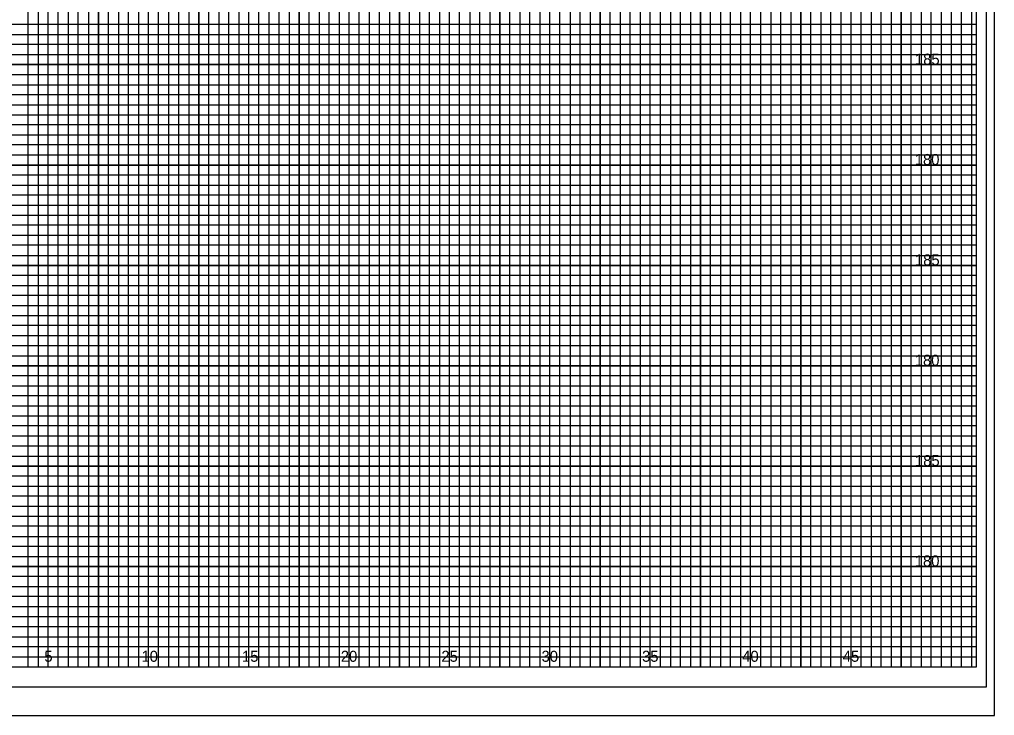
# Model space of a CAD drawing. Extents: x -4 to 103, y -2 to 209.
# Drawn here: x 54.82 to 103.4, y 68.4 to 103.08 of the extents above; entities that cross this region are included whole.
import ezdxf

# ---------------------------------------------------------------- set-up
doc = ezdxf.new("R2010")
doc.units = 0
for name, color, linetype in [('Old_Level_10', 7, 'Continuous'), ('Old_Level_16', 7, 'Continuous'), ('Old_Level_3', 7, 'Continuous'), ('Old_Level_4', 7, 'Continuous'), ('Old_Level_5', 7, 'Continuous'), ('Old_Level_6', 7, 'Continuous'), ('Old_Level_8', 7, 'Continuous'), ('Prop Dimension', 7, 'Continuous'), ('Prop XS Subgrade Earthwork', 7, 'Continuous')]:
    doc.layers.add(name, color=color, linetype=linetype)

msp = doc.modelspace()

# ---------------------------------------------------------------- linework, layer by layer
at = {"layer": 'Old_Level_10'}
for p, q in [((56.25, 70.825), (56.25, 135.825)), ((58.75, 70.825), (58.75, 135.825)), ((61.25, 70.825), (61.25, 135.825)), ((63.75, 70.825), (63.75, 135.825)), ((66.25, 70.825), (66.25, 135.825)), ((68.75, 70.825), (68.75, 135.825)), ((71.25, 70.825), (71.25, 135.825)), ((73.75, 70.825), (73.75, 135.825)), ((91.25, 70.825), (91.25, 134.25)), ((93.75, 70.825), (93.75, 134.25)), ((96.25, 70.825), (96.25, 134.25)), ((98.75, 70.825), (98.75, 134.25)), ((101.25, 70.825), (101.25, 134.25)), ((76.25, 70.825), (76.25, 132.825)), ((78.75, 70.825), (78.75, 132.825)), ((81.25, 70.825), (81.25, 132.825)), ((83.75, 70.825), (83.75, 132.825)), ((86.25, 70.825), (86.25, 132.825)), ((88.75, 70.825), (88.75, 132.825)), ((0, 100.825), (102.5, 100.825)), ((0, 98.325), (102.5, 98.325)), ((0, 95.825), (102.5, 95.825)), ((0, 93.325), (102.5, 93.325)), ((0, 90.825), (102.5, 90.825)), ((0, 88.325), (102.5, 88.325)), ((0, 85.825), (102.5, 85.825)), ((0, 83.325), (102.5, 83.325)), ((0, 80.825), (102.5, 80.825)), ((0, 78.325), (102.5, 78.325)), ((0, 75.825), (102.5, 75.825)), ((0, 73.325), (102.5, 73.325))]:
    msp.add_line(p, q, dxfattribs=at)
at = {"layer": 'Old_Level_3'}
msp.add_line((-3.5, 68.4), (103.4, 68.4), dxfattribs=at)
at = {"layer": 'Old_Level_4'}
msp.add_lwpolyline([(103, 136.825), (-2.8, 136.825), (-2.8, 69.825), (103, 69.825)], close=True, dxfattribs=at)
at = {"layer": 'Old_Level_5'}
msp.add_lwpolyline([(103.4, 138.225), (-3.5, 138.225), (-3.5, 68.4), (103.4, 68.4)], close=True, dxfattribs=at)
at = {"layer": 'Old_Level_6'}
msp.add_lwpolyline([(102.5, 135.825), (0, 135.825), (0, 70.825), (102.5, 70.825)], close=True, dxfattribs=at)
at = {"layer": 'Old_Level_8'}
for points in [[(56.25, 70.825), (56.25, 135.825)], [(58.75, 135.825), (58.75, 70.825), (61.25, 70.825), (61.25, 135.825)], [(63.75, 135.825), (63.75, 70.825), (66.25, 70.825), (66.25, 135.825)], [(68.75, 135.825), (68.75, 70.825), (71.25, 70.825), (71.25, 135.825)], [(73.75, 135.825), (73.75, 70.825), (76.25, 70.825), (76.25, 132.825)], [(88.75, 132.825), (88.75, 70.825), (91.25, 70.825), (91.25, 134.25)], [(93.75, 134.25), (93.75, 70.825), (96.25, 70.825), (96.25, 134.25)], [(98.75, 134.25), (98.75, 70.825), (101.25, 70.825), (101.25, 134.25)], [(78.75, 132.825), (78.75, 70.825), (81.25, 70.825), (81.25, 132.825)], [(83.75, 132.825), (83.75, 70.825), (86.25, 70.825), (86.25, 132.825)], [(0, 98.325), (102.5, 98.325), (102.5, 100.825), (0, 100.825)], [(0, 93.325), (102.5, 93.325), (102.5, 95.825), (0, 95.825)], [(0, 88.325), (102.5, 88.325), (102.5, 90.825), (0, 90.825)], [(0, 83.325), (102.5, 83.325), (102.5, 85.825), (0, 85.825)], [(0, 78.325), (102.5, 78.325), (102.5, 80.825), (0, 80.825)], [(0, 73.325), (102.5, 73.325), (102.5, 75.825), (0, 75.825)]]:
    msp.add_lwpolyline(points, dxfattribs=at)
at = {"layer": 'Prop Dimension'}
for points in [[(54.75, 70.825), (55.25, 70.825), (55.25, 135.825)], [(55.75, 135.825), (55.75, 70.825), (56.75, 70.825), (56.75, 135.825)], [(57.25, 135.825), (57.25, 70.825), (57.75, 70.825), (57.75, 135.825)], [(58.25, 135.825), (58.25, 70.825), (59.25, 70.825), (59.25, 135.825)], [(59.75, 135.825), (59.75, 70.825), (60.25, 70.825), (60.25, 135.825)], [(60.75, 135.825), (60.75, 70.825), (61.75, 70.825), (61.75, 135.825)], [(62.25, 135.825), (62.25, 70.825), (62.75, 70.825), (62.75, 135.825)], [(63.25, 135.825), (63.25, 70.825), (64.25, 70.825), (64.25, 135.825)], [(64.75, 135.825), (64.75, 70.825), (65.25, 70.825), (65.25, 135.825)], [(65.75, 135.825), (65.75, 70.825), (66.75, 70.825), (66.75, 135.825)], [(67.25, 135.825), (67.25, 70.825), (67.75, 70.825), (67.75, 135.825)], [(68.25, 135.825), (68.25, 70.825), (69.25, 70.825), (69.25, 135.825)], [(69.75, 135.825), (69.75, 70.825), (70.25, 70.825), (70.25, 135.825)], [(70.75, 135.825), (70.75, 70.825), (71.75, 70.825), (71.75, 135.825)], [(72.25, 135.825), (72.25, 70.825), (72.75, 70.825), (72.75, 135.825)], [(73.25, 135.825), (73.25, 70.825), (74.25, 70.825), (74.25, 132.825)], [(89.75, 132.825), (89.75, 70.825), (90.25, 70.825), (90.25, 134.25)], [(90.75, 134.25), (90.75, 70.825), (91.75, 70.825), (91.75, 134.25)], [(92.25, 134.25), (92.25, 70.825), (92.75, 70.825), (92.75, 134.25)], [(93.25, 134.25), (93.25, 70.825), (94.25, 70.825), (94.25, 134.25)], [(94.75, 134.25), (94.75, 70.825), (95.25, 70.825), (95.25, 134.25)], [(95.75, 134.25), (95.75, 70.825), (96.75, 70.825), (96.75, 134.25)], [(97.25, 134.25), (97.25, 70.825), (97.75, 70.825), (97.75, 134.25)], [(98.25, 134.25), (98.25, 70.825), (99.25, 70.825), (99.25, 134.25)], [(99.75, 134.25), (99.75, 70.825), (100.25, 70.825), (100.25, 134.25)], [(100.25, 134.25), (100.75, 134.25), (100.75, 70.825), (101.75, 70.825), (101.75, 134.25), (102.25, 134.25), (102.25, 70.825)], [(74.75, 132.825), (74.75, 70.825), (75.25, 70.825), (75.25, 132.825)], [(75.75, 132.825), (75.75, 70.825), (76.75, 70.825), (76.75, 132.825)], [(77.25, 132.825), (77.25, 70.825), (77.75, 70.825), (77.75, 132.825)], [(78.25, 132.825), (78.25, 70.825), (79.25, 70.825), (79.25, 132.825)], [(79.75, 132.825), (79.75, 70.825), (80.25, 70.825), (80.25, 132.825)], [(80.75, 132.825), (80.75, 70.825), (81.75, 70.825), (81.75, 132.825)], [(82.25, 132.825), (82.25, 70.825), (82.75, 70.825), (82.75, 132.825)], [(83.25, 132.825), (83.25, 70.825), (84.25, 70.825), (84.25, 132.825)], [(84.75, 132.825), (84.75, 70.825), (85.25, 70.825), (85.25, 132.825)], [(85.75, 132.825), (85.75, 70.825), (86.75, 70.825), (86.75, 132.825)], [(87.25, 132.825), (87.25, 70.825), (87.75, 70.825), (87.75, 132.825)], [(88.25, 132.825), (88.25, 70.825), (89.25, 70.825), (89.25, 132.825)], [(0, 102.325), (102.5, 102.325), (102.5, 102.825), (0, 102.825)], [(0, 101.325), (102.5, 101.325), (102.5, 101.825), (0, 101.825)], [(0, 99.825), (102.5, 99.825), (102.5, 100.325), (0, 100.325)], [(0, 98.825), (102.5, 98.825), (102.5, 99.325), (0, 99.325)], [(0, 97.325), (102.5, 97.325), (102.5, 97.825), (0, 97.825)], [(0, 96.325), (102.5, 96.325), (102.5, 96.825), (0, 96.825)], [(0, 94.825), (102.5, 94.825), (102.5, 95.325), (0, 95.325)], [(0, 93.825), (102.5, 93.825), (102.5, 94.325), (0, 94.325)], [(0, 92.325), (102.5, 92.325), (102.5, 92.825), (0, 92.825)], [(0, 91.325), (102.5, 91.325), (102.5, 91.825), (0, 91.825)], [(0, 89.825), (102.5, 89.825), (102.5, 90.325), (0, 90.325)], [(0, 88.825), (102.5, 88.825), (102.5, 89.325), (0, 89.325)], [(0, 87.325), (102.5, 87.325), (102.5, 87.825), (0, 87.825)], [(0, 86.325), (102.5, 86.325), (102.5, 86.825), (0, 86.825)], [(0, 84.825), (102.5, 84.825), (102.5, 85.325), (0, 85.325)], [(0, 83.825), (102.5, 83.825), (102.5, 84.325), (0, 84.325)], [(0, 82.325), (102.5, 82.325), (102.5, 82.825), (0, 82.825)], [(0, 81.325), (102.5, 81.325), (102.5, 81.825), (0, 81.825)], [(0, 79.825), (102.5, 79.825), (102.5, 80.325), (0, 80.325)], [(0, 78.825), (102.5, 78.825), (102.5, 79.325), (0, 79.325)], [(0, 77.325), (102.5, 77.325), (102.5, 77.825), (0, 77.825)], [(0, 76.325), (102.5, 76.325), (102.5, 76.825), (0, 76.825)], [(0, 74.825), (102.5, 74.825), (102.5, 75.325), (0, 75.325)], [(0, 73.825), (102.5, 73.825), (102.5, 74.325), (0, 74.325)], [(0, 72.325), (102.5, 72.325), (102.5, 72.825), (0, 72.825)], [(0, 71.325), (102.5, 71.325), (102.5, 71.825), (0, 71.825)]]:
    msp.add_lwpolyline(points, dxfattribs=at)

# ---------------------------------------------------------------- texts
at = {"layer": 'Old_Level_16'}
for s, p in [('5', (56.0574, 71.075)), ('10', (60.8971, 71.075)), ('15', (65.9057, 71.075)), ('20', (70.8312, 71.075)), ('25', (75.8399, 71.075)), ('30', (80.8312, 71.075)), ('35', (85.8399, 71.075)), ('40', (90.8313, 71.075)), ('45', (95.8399, 71.075))]:
    msp.add_text(s, height=0.55, dxfattribs=at).set_placement(p)
at = {"layer": 'Prop XS Subgrade Earthwork'}
for s, p in [('185', (99.4383, 100.825)), ('180', (99.4296, 95.825)), ('185', (99.4383, 90.825)), ('180', (99.4296, 85.825)), ('185', (99.4383, 80.825)), ('180', (99.4296, 75.825))]:
    msp.add_text(s, height=0.55, dxfattribs=at).set_placement(p)

doc.saveas('drawing.dxf')
